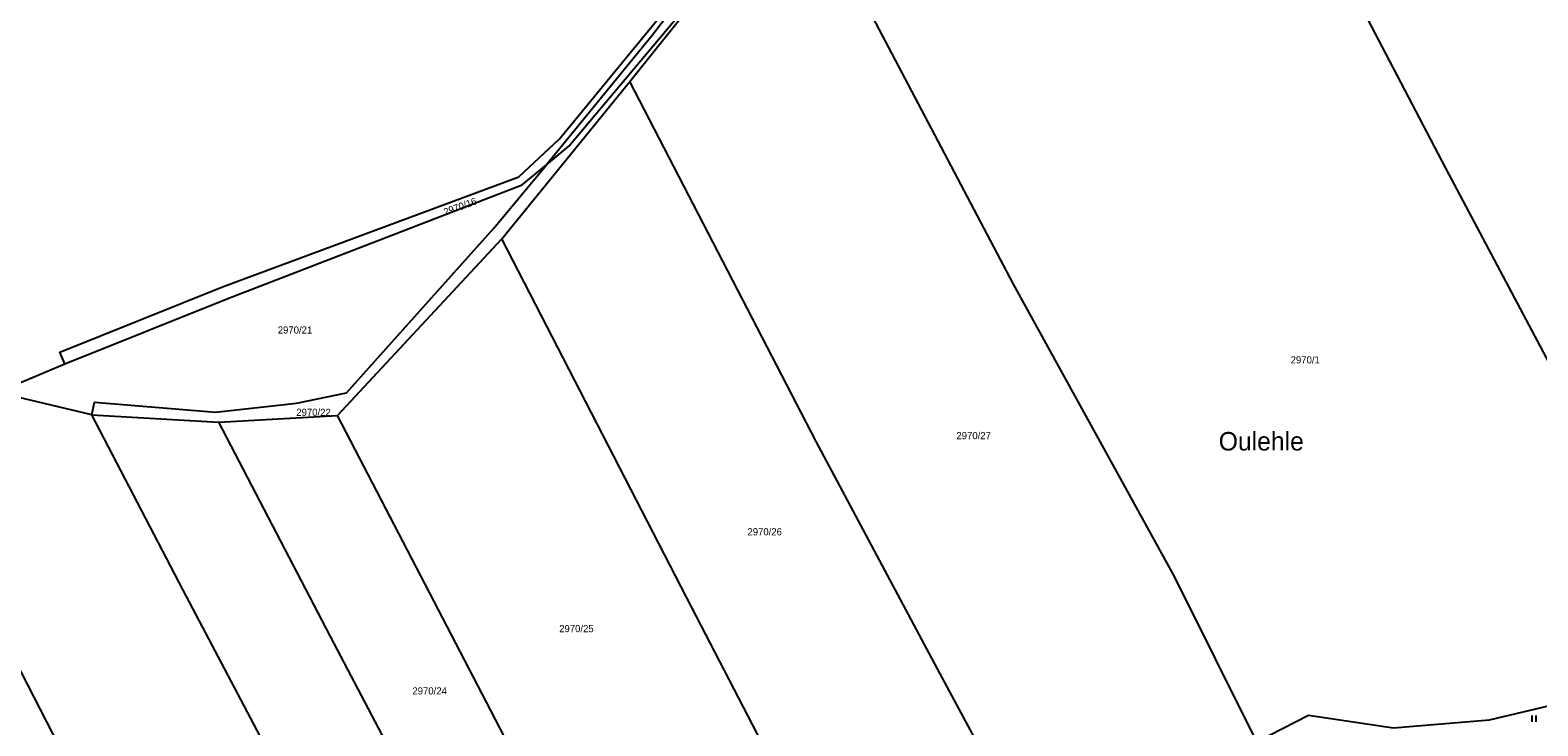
# Model space of a CAD drawing. Extents: x -776734 to -748832, y -1118122 to -976986.
# Drawn here: x -754304.9 to -753945.5, y -1113776.6 to -1113610.9 of the extents above; entities that cross this region are included whole.
import ezdxf

# ---------------------------------------------------------------- set-up
doc = ezdxf.new("R2010")
doc.units = 0
for name, color, linetype in [('KM_Hranice parcel', 7, 'Continuous'), ('KM_Parcelní čísla', 7, 'Continuous'), ('KM_Pop  PČ popisy', 7, 'Continuous'), ('KM_Značky kultur', 7, 'Continuous')]:
    doc.layers.add(name, color=color, linetype=linetype)

msp = doc.modelspace()

# ---------------------------------------------------------------- linework, layer by layer
at = {"layer": 'KM_Hranice parcel'}
for p, q in [((-754162, -1113623.09), (-754122.19, -1113573.44)), ((-754192.53, -1113660.57), (-754162, -1113623.09)), ((-754231.66, -1113702.65), (-754192.53, -1113660.57)), ((-754290.21, -1113702.49), (-754259.94, -1113704.24)), ((-754259.94, -1113704.24), (-754231.66, -1113702.65))]:
    msp.add_line(p, q, dxfattribs=at)
for points in [[(-754296.67, -1113690.34), (-754297.85, -1113687.55), (-754259.06, -1113672.02), (-754188.45, -1113645.8), (-754178.78, -1113636.77), (-754136.25, -1113584.93), (-754066.43, -1113499.99)], [(-754062.35, -1113499.91), (-754089.12, -1113528.96), (-754113.39, -1113558.52), (-754139.33, -1113589.56), (-754156.63, -1113612.11), (-754181.86, -1113642.92)], [(-753901.25, -1113770.28), (-753920.25, -1113734.23), (-753941.47, -1113692.62), (-753967.45, -1113643.7), (-753989.63, -1113601.3), (-754038.29, -1113512.02)], [(-754181.86, -1113642.92), (-754176.53, -1113638.52), (-754133, -1113586.6), (-754122.19, -1113573.44)], [(-754122.19, -1113573.44), (-754070.59, -1113671.33), (-754032.26, -1113741.04), (-754012.65, -1113780.4)], [(-754064.58, -1113807.73), (-754088.01, -1113764.21), (-754117.58, -1113708.88), (-754162, -1113623.09)], [(-754296.67, -1113690.34), (-754257.83, -1113674.75), (-754187.66, -1113647.72), (-754181.86, -1113642.92)], [(-754290.21, -1113702.49), (-754289.62, -1113699.51), (-754260.74, -1113701.87), (-754241.43, -1113699.75), (-754229.51, -1113697.25), (-754194.44, -1113658.03), (-754181.86, -1113642.92)], [(-754104.86, -1113829.84), (-754121.36, -1113798.21), (-754148.4, -1113746.13), (-754192.53, -1113660.57)], [(-754313.26, -1113697.42), (-754311.77, -1113696.73), (-754296.67, -1113690.34)], [(-754290.21, -1113702.49), (-754309.61, -1113697.91), (-754313.26, -1113697.42)], [(-754214.04, -1113848.92), (-754239.4, -1113799.37), (-754268.43, -1113744.24), (-754290.21, -1113702.49)], [(-754189.51, -1113840.37), (-754205.49, -1113808.35), (-754233.36, -1113755.33), (-754259.94, -1113704.24)], [(-754164.76, -1113832.3), (-754190.89, -1113781), (-754231.66, -1113702.65)], [(-754254.49, -1113867.61), (-754291.87, -1113793.3), (-754334.19, -1113711.19)], [(-754012.65, -1113780.4), (-754000.2, -1113774.02), (-753979.95, -1113777.07), (-753957.06, -1113775.16), (-753936.3, -1113770.26), (-753901.25, -1113770.28)]]:
    msp.add_lwpolyline(points, dxfattribs=at)
at = {"layer": 'KM_Značky kultur'}
for p, q in [((-753946.931, -1113775.63), (-753946.931, -1113774.13)), ((-753945.93, -1113775.63), (-753945.93, -1113774.13))]:
    msp.add_line(p, q, dxfattribs=at)

# ---------------------------------------------------------------- texts
at = {"layer": 'KM_Parcelní čísla'}
msp.add_text('2970/16', height=1.7, rotation=20, dxfattribs=at).set_placement((-754206.029, -1113655.068))
for s, p in [('2970/21', (-754245.91, -1113683.14)), ('2970/1', (-754004.47, -1113690.25)), ('2970/22', (-754241.49, -1113702.75)), ('2970/27', (-754084.14, -1113708.3)), ('2970/26', (-754133.95, -1113731.21)), ('2970/25', (-754178.83, -1113754.28)), ('2970/24', (-754213.82, -1113769.12))]:
    msp.add_text(s, height=1.7, dxfattribs=at).set_placement(p)
at = {"layer": 'KM_Pop  PČ popisy'}
msp.add_text('Oulehle', height=4.4, dxfattribs=at).set_placement((-754021.616, -1113710.99))

doc.saveas('drawing.dxf')
